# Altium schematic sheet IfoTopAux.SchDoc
size B; DocumentNumber: 1; SheetNumber: 1; SheetTotal: 8; pInstance: Corner
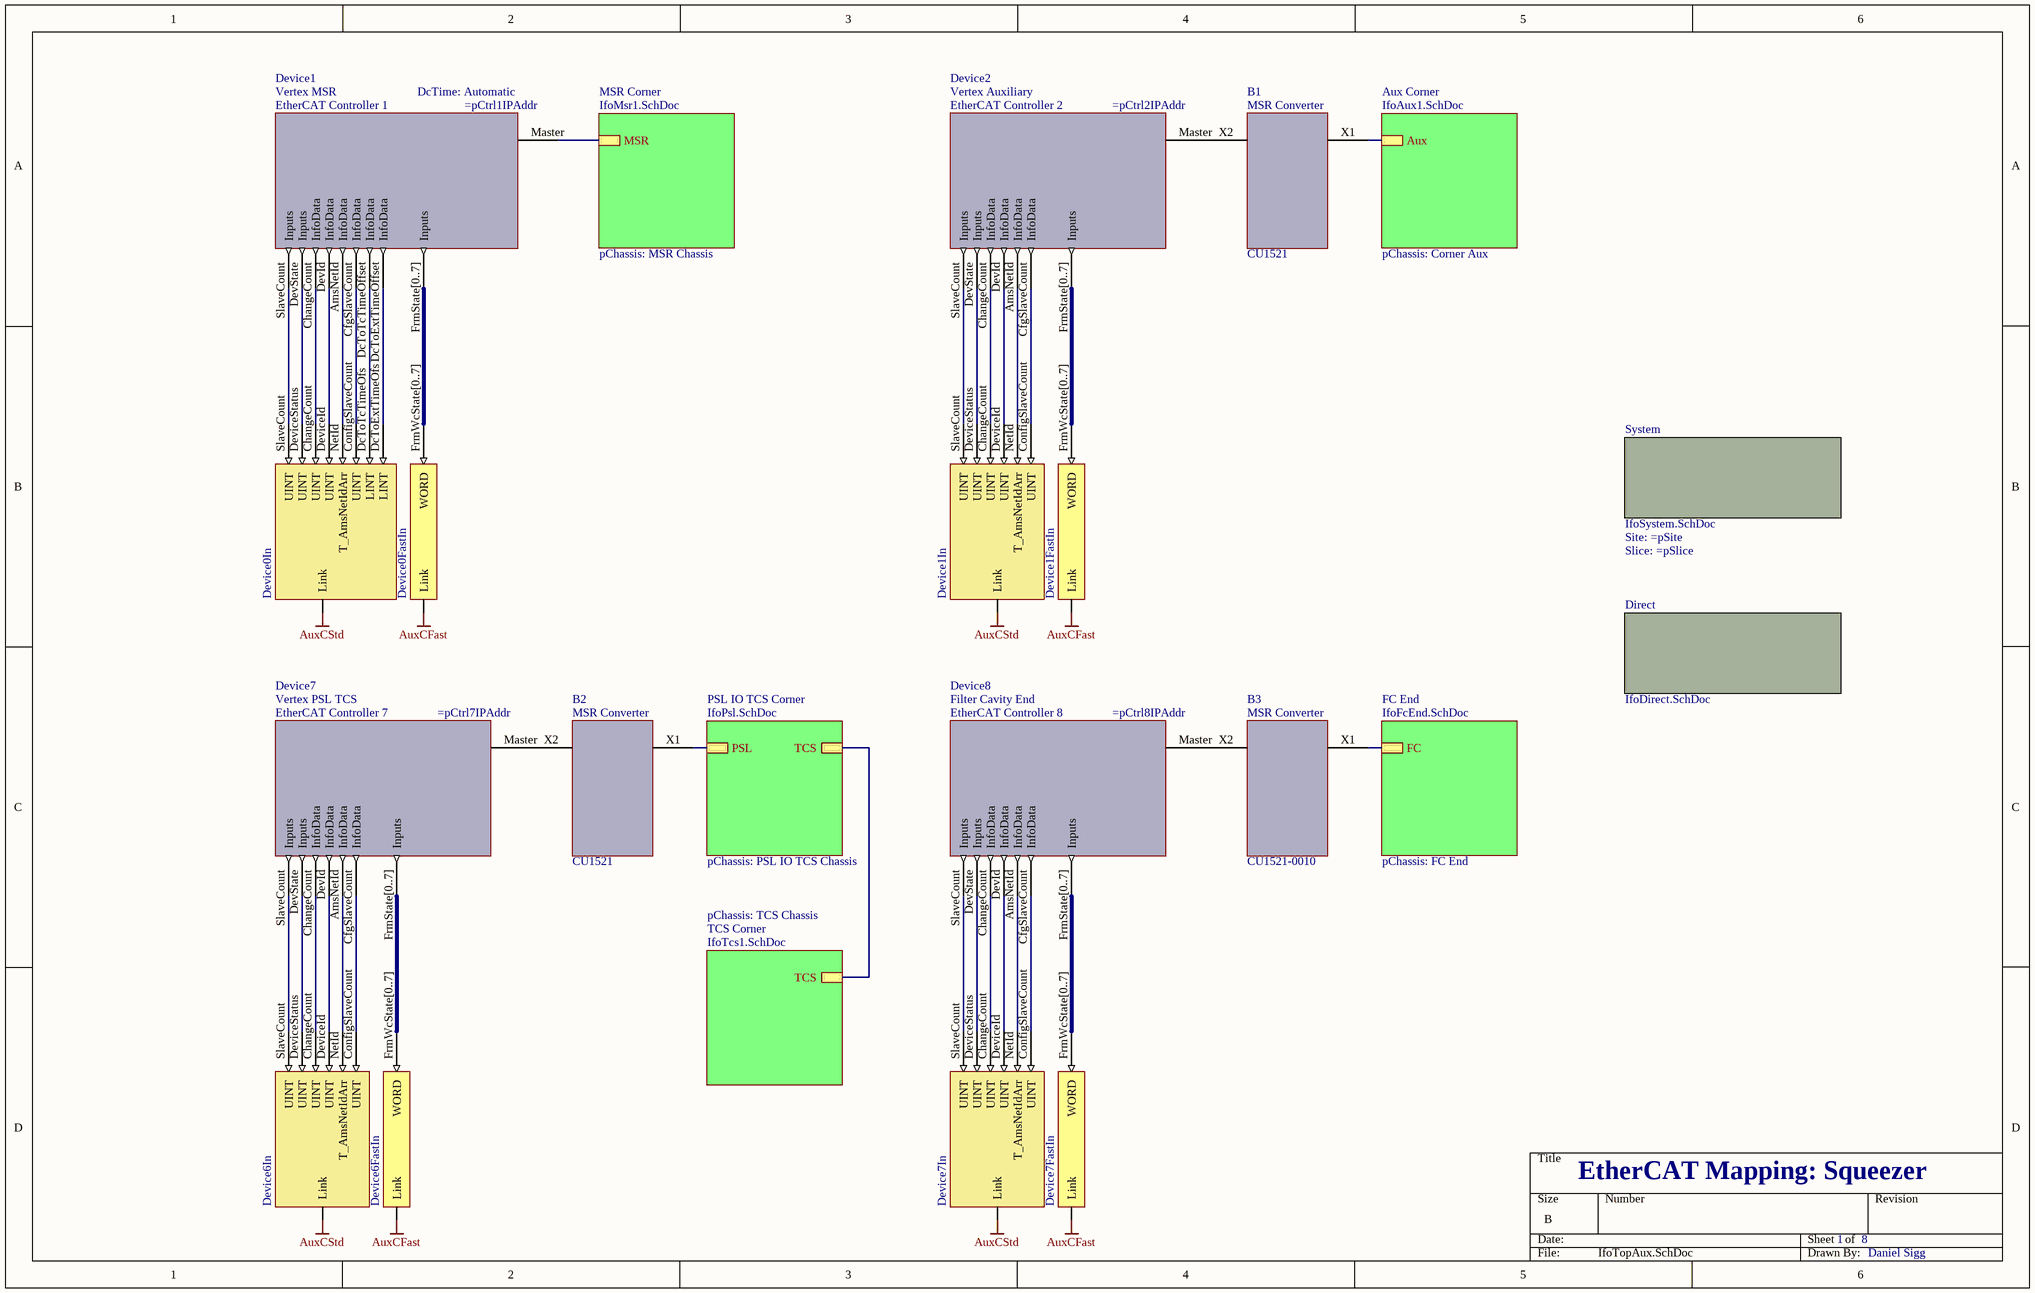
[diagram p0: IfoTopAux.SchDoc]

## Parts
B1  MSR Converter  Part Number: CU1521  (mechanical)
B2  MSR Converter  Part Number: CU1521  (mechanical)
B3  MSR Converter  Part Number: CU1521-0010  (mechanical)
Device1  Vertex MSR  DcTime: Automatic  DeviceDesc: EtherCAT Controller 1  (mechanical)
Device2  Vertex Auxiliary  DeviceDesc: EtherCAT Controller 2  (mechanical)
Device7  Vertex PSL TCS  DeviceDesc: EtherCAT Controller 7  (mechanical)
Device8  Filter Cavity End  DeviceDesc: EtherCAT Controller 8  (mechanical)
V81  Device0In  (no BOM)
V82  Device0FastIn  (no BOM)
V83  Device1In  (no BOM)
V84  Device1FastIn  (no BOM)
V85  Device6In  (no BOM)
V86  Device6FastIn  (no BOM)
V87  Device7In  (no BOM)
V88  Device7FastIn  (no BOM)

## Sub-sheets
Aux Corner = IfoAux1.SchDoc: Aux  | pChassis: Corner Aux
Direct = IfoDirect.SchDoc: no entries
FC End = IfoFcEnd.SchDoc: FC  | pChassis: FC End
MSR Corner = IfoMsr1.SchDoc: MSR  | pChassis: MSR Chassis
PSL IO TCS Corner = IfoPsl.SchDoc: PSL, TCS  | pChassis: PSL IO TCS Chassis
System = IfoSystem.SchDoc: no entries  | Site: =pSite; Slice: =pSlice
TCS Corner = IfoTcs1.SchDoc: TCS  | pChassis: TCS Chassis

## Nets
AuxCFast: V82.?1(Link) V84.?1(Link) V86.?1(Link) V88.?1(Link)
AuxCStd: V81.?1(Link) V83.?1(Link) V85.?1(Link) V87.?1(Link)
NetB1_X1: B1.X1(B) ; sheet Aux Corner/Aux
NetB1_X2: B1.X2(A) Device2.Master(B)
NetB2_X1: B2.X1(B) ; sheet PSL IO TCS Corner/PSL
NetB2_X2: B2.X2(A) Device7.Master(B)
NetB3_X1: B3.X1(B) ; sheet FC End/FC
NetB3_X2: B3.X2(A) Device8.Master(B)
NetDevice1_AmsNetId: Device1.AmsNetId(InfoData) V81.NetId(T_AmsNetIdArr)
NetDevice1_CfgSlaveCount: Device1.CfgSlaveCount(InfoData) V81.ConfigSlaveCount(UINT)
NetDevice1_ChangeCount: Device1.ChangeCount(InfoData) V81.ChangeCount(UINT)
NetDevice1_DcToExtTimeOffset: Device1.DcToExtTimeOffset(InfoData) V81.DcToExtTimeOfs(LINT)
NetDevice1_DcToTcTimeOffset: Device1.DcToTcTimeOffset(InfoData) V81.DcToTcTimeOfs(LINT)
NetDevice1_DevId: Device1.DevId(InfoData) V81.DeviceId(UINT)
NetDevice1_DevState: Device1.DevState(Inputs) V81.DeviceStatus(UINT)
NetDevice1_FrmState[0..7]: Device1.FrmState[0..7](Inputs) V82.FrmWcState[0..7](WORD)
NetDevice1_Master: Device1.Master(B) ; sheet MSR Corner/MSR
NetDevice1_SlaveCount: Device1.SlaveCount(Inputs) V81.SlaveCount(UINT)
NetDevice2_AmsNetId: Device2.AmsNetId(InfoData) V83.NetId(T_AmsNetIdArr)
NetDevice2_CfgSlaveCount: Device2.CfgSlaveCount(InfoData) V83.ConfigSlaveCount(UINT)
NetDevice2_ChangeCount: Device2.ChangeCount(InfoData) V83.ChangeCount(UINT)
NetDevice2_DevId: Device2.DevId(InfoData) V83.DeviceId(UINT)
NetDevice2_DevState: Device2.DevState(Inputs) V83.DeviceStatus(UINT)
NetDevice2_FrmState[0..7]: Device2.FrmState[0..7](Inputs) V84.FrmWcState[0..7](WORD)
NetDevice2_SlaveCount: Device2.SlaveCount(Inputs) V83.SlaveCount(UINT)
NetDevice7_AmsNetId: Device7.AmsNetId(InfoData) V85.NetId(T_AmsNetIdArr)
NetDevice7_CfgSlaveCount: Device7.CfgSlaveCount(InfoData) V85.ConfigSlaveCount(UINT)
NetDevice7_ChangeCount: Device7.ChangeCount(InfoData) V85.ChangeCount(UINT)
NetDevice7_DevId: Device7.DevId(InfoData) V85.DeviceId(UINT)
NetDevice7_DevState: Device7.DevState(Inputs) V85.DeviceStatus(UINT)
NetDevice7_FrmState[0..7]: Device7.FrmState[0..7](Inputs) V86.FrmWcState[0..7](WORD)
NetDevice7_SlaveCount: Device7.SlaveCount(Inputs) V85.SlaveCount(UINT)
NetDevice8_AmsNetId: Device8.AmsNetId(InfoData) V87.NetId(T_AmsNetIdArr)
NetDevice8_CfgSlaveCount: Device8.CfgSlaveCount(InfoData) V87.ConfigSlaveCount(UINT)
NetDevice8_ChangeCount: Device8.ChangeCount(InfoData) V87.ChangeCount(UINT)
NetDevice8_DevId: Device8.DevId(InfoData) V87.DeviceId(UINT)
NetDevice8_DevState: Device8.DevState(Inputs) V87.DeviceStatus(UINT)
NetDevice8_FrmState[0..7]: Device8.FrmState[0..7](Inputs) V88.FrmWcState[0..7](WORD)
NetDevice8_SlaveCount: Device8.SlaveCount(Inputs) V87.SlaveCount(UINT)
(unnamed): sheet PSL IO TCS Corner/TCS, sheet TCS Corner/TCS

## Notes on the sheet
- EtherCAT Mapping: Squeezer
- Daniel Sigg

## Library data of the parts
B1 = MediaConverterCAT5toFiber: EtherCAT Media Converter; BoxType: Box; BoxNextB: RINAXMQE; BoxPrev: HZXVVAEU; PortPrevFull: 1000/; Fullname: TIID^Vertex Auxiliary (EtherCAT)^MSR Converter (CU1521); BoxAddr: 1001; Disabled: False
B2 = MediaConverterCAT5toFiber: EtherCAT Media Converter; BoxType: Box; BoxNextB: MGVQPUOL; BoxPrev: KDVQDHRV; PortPrevFull: 1000/; Fullname: TIID^Vertex PSL TCS (EtherCAT)^MSR Converter (CU1521); BoxAddr: 1001; Disabled: False
B3 = MediaConverterCAT5toFiber: EtherCAT Media Converter; BoxType: Box; BoxNextB: PXLUFAHI; BoxPrev: MWLZWHYE; PortPrevFull: 1000/; Fullname: TIID^Filter Cavity End (EtherCAT)^MSR Converter (CU1521-0010); BoxAddr: 1001; Disabled: False
Device1 = EtherCATMasterTimingB: EtherCAT Master; Part Number: FC9022; DeviceData: 0001053F992A; BoxNextB: DRMHDDTT; Fullname: TIID^Vertex MSR (EtherCAT); BoxSubType: 111; Disabled: False
Device2 = EtherCATMaster: EtherCAT Master; Part Number: FC9022; DeviceData: 0001053F992B; BoxNextB: NSXPNOPV; Fullname: TIID^Vertex Auxiliary (EtherCAT); BoxSubType: 111; Disabled: False
Device7 = EtherCATMaster: EtherCAT Master; Part Number: FC9022; DeviceData: 0001053F9929; BoxNextB: BGADWTKS; Fullname: TIID^Vertex PSL TCS (EtherCAT); BoxSubType: 111; Disabled: False
Device8 = EtherCATMaster: EtherCAT Master; Part Number: FC9022; DeviceData: 0001053F9928; BoxNextB: TQXSIIBF; Fullname: TIID^Filter Cavity End (EtherCAT); BoxSubType: 111; Disabled: False
V81 = PLCInfo_MasterInfoInStructB: MasterInfoInStruct; BoxType: Variable; Instance: H1AuxCorner Instance; PLC: H1AuxCorner; Task: AuxCStd
V82 = PLCInfo_MasterInfoFastInStruct: MasterInfoFastInStruct; BoxType: Variable; Instance: H1AuxCorner Instance; PLC: H1AuxCorner; Task: AuxCFast
V83 V85 V87 = PLCInfo_MasterInfoInStruct: MasterInfoInStruct; PLC: H1AuxCorner; Task: AuxCStd; BoxType: Variable; Instance: H1AuxCorner Instance
V84 V86 V88 = PLCInfo_MasterInfoFastInStruct: MasterInfoFastInStruct; PLC: H1AuxCorner; Task: AuxCFast; BoxType: Variable; Instance: H1AuxCorner Instance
